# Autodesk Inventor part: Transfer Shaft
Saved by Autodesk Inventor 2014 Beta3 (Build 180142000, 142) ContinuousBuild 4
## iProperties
Created: 2011-01
Part Number: Transfer Shaft
Material: Steel
Document SubType Name: Modeling
Designer: Beta-8540w
Density: 1 g/cm^3
Appearance: Steel
CustomPartVersion: 1
Author: Beta-8540w
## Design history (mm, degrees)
sketch "Main Sketch"
  geometry: L1 (0, 0)-(51, 0) reference; L2 (0, 0)-(0, 5); L3 (0, 5)-(10, 5); L4 (10, 5)-(10, 6); L5 (10, 6)-(13, 6); L6 (13, 6)-(13, 12.5); L7 (25, 12.5)-(25, 6); L8 (13, 12.5)-(25, 12.5); L9 (41, 6)-(41, 5); L10 (25, 6)-(41, 6); L11 (51, 5)-(51, 0); L12 (41, 5)-(51, 5)
  constraints: 24 end point, 7 horizontal, 6 vertical
  dimensions: "d3" = 10 diameter of L3 L1 (derived); "d4" = 12 diameter of L5 L1 (derived); "d5" = 25 diameter of L8 L1 (derived); "d6" = 12 diameter of L10 L1 (derived); "d7" = 10 diameter of L12 L1 (derived)
revolve "Revolution1" sketch "Main Sketch" stored, may be unused: angle "d8" = 0 deg
chamfer "Chamfer1" distance "d9" = 0.3; stored, may be unused: second distance "d10" = 0.125, angle "d11" = 45 deg
chamfer "Chamfer2" distance "d12" = 0.3; stored, may be unused: second distance "d13" = 0.125, angle "d14" = 45 deg
node "Spur Gear Teeth1"
node "Keyway1"
body "Solid1"
feature "Spur Gear1"
feature "Shaft Keyway"
other parameters: "d0" = 0, "d1" = 0, "d2" = 0
